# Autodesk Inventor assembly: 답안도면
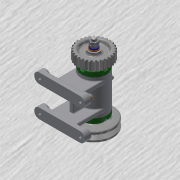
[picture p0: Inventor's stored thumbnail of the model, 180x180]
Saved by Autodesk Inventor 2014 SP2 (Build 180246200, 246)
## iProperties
Created: 2015-11
Part Number: 답안도면
Document SubType Name: Assembly
Designer: 702
Author: 702
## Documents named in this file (16)
- C:\Users\702\Desktop\451109V1008\답안도면.iam
- C:\Users\702\Desktop\451109V1008\본체.ipt
- C:\Users\702\Desktop\451109V1008\베어링 15 x 32 x 9.ipt
- C:\Users\702\Desktop\451109V1008\축.ipt
- C:\Users\702\Desktop\451109V1008\키 3 x 3 x 12.ipt
- C:\Users\702\Desktop\451109V1008\커버.ipt
- C:\Users\702\Desktop\451109V1008\볼트 M4 x 12.ipt
- C:\Users\702\Desktop\451109V1008\오일 실 15 25 7.ipt
- C:\Users\702\Desktop\451109V1008\V벨트풀리.ipt
- C:\Users\702\Desktop\451109V1008\스퍼기어.ipt
- C:\Users\702\Desktop\451109V1008\너트 M 8.ipt
- C:\Users\702\Desktop\451109V1008\스프링와셔 8.ipt
- C:\Users\702\Desktop\451109V1008\와셔 8x17.ipt
- C:\Users\702\Desktop\451109V1008\니플 M 6 x 0.75.ipt
- C:\Users\702\Desktop\451109V1008\볼트 M 6 x 8.ipt
- C:\Users\702\Desktop\451109V1008\와셔 6x11.5.ipt
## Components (11 placed, 3 different names)
1. KS B 2023 6002 - 15 x 32 x 9:1
2. KS B 2023 6002 - 15 x 32 x 9:2
3. V벨트풀리:1
4. ISO 4762 M4 x 12:1
5. ISO 4762 M4 x 12:2
6. ISO 4762 M4 x 12:3
7. ISO 4762 M4 x 12:4
8. ISO 4762 M4 x 12:5
9. ISO 4762 M4 x 12:6
10. ISO 4762 M4 x 12:7
11. ISO 4762 M4 x 12:8
